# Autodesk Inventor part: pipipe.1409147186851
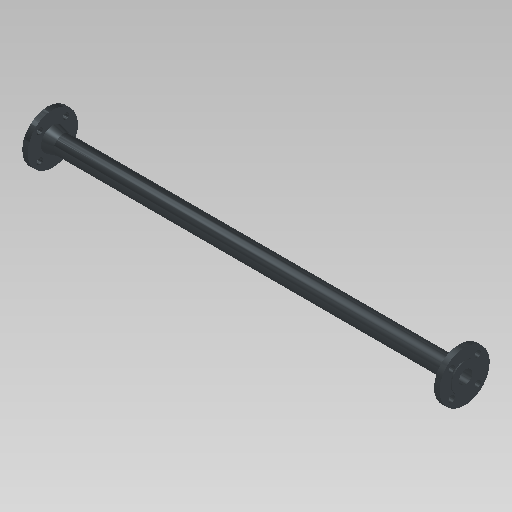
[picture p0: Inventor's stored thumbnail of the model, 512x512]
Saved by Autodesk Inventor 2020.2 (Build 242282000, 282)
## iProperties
Manager: www.cadconsulting.pl
Company: Fabian Stasiak CAD Consulting
IsCustomPart: 1
NAME: PIPING: ISO 2531 Pipe with Integrally Cast Flanges
DATA: <meta><inlinegroups number="1" deflen="50"></inlinegroups><connections number="2"></connections><angles><a>3.14159265358979</a></angles></meta>
Created: 2014-08
Material: Żeliwo sferoidalne
Description: Rury, łączniki, akcesoria z żeliwa sferoidalnego i ich złącza do zastosowań w instalacjach wodnych lub gazowych - Rura odlewana wraz z kołnierzami
Document SubType Name: Modeling
Standard: ISO 2531
Designer: F.Stasiak
Standard Revision: Fifth edition 1998-08-15
Standards Organization: ISO
Language: pl-PL
Size Designation: DN40 PN 10 - 500
Categories: <MemberInstance><Categories><Category DisplayName="Rury cienko- i grubościenne" InternalName="4347fa0f-2144-441d-94cd-e3e15c92b736" Mnemonic="TUBEANDPIPE"><Cate
Stock Number: ISO 2531 Rura odlewana wraz z kołnierzami DN40 PN 10
Density: 7.15 g/cm^3
Appearance: Ciemnoszary
Catalog Web Link: www.expertbooks.pl
L: 1250,000 mm
PL: 1250,000 mm
Author: F.Stasiak
Subject: Zbiór ćwiczeń. Autodesk Inventor 2020. Kurs Professional
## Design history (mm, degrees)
sketch "Sketch1"
  geometry: L1 (0, 0)-(-625, 0); L2 (-625, 0)-(-625, 20); L3 (-1201.144, 27)-(-48.856, 27); L4 (-48.856, 27)-(-19, 35); L5 (-19, 35)-(-19, 75); L6 (-19, 75)-(-3, 75); L7 (-3, 75)-(-3, 42); L8 (-3, 42)-(0, 42); L9 (0, 42)-(0, 20); L10 (-1250, 20)-(0, 20); L11 (0, 20)-(0, 0); L12 (-1201.144, 27)-(-1231, 35); L13 (-1231, 35)-(-1231, 75); L14 (-1231, 75)-(-1247, 75); L15 (-1247, 75)-(-1247, 42); L16 (-1247, 42)-(-1250, 42); L17 (-1250, 42)-(-1250, 20); L18 (-1250, 20)-(-1250, 0); 2 further points
  constraints: 36 end point, 9 symmetric about line, 4 parallel, 2 coincident, 2 horizontal, 2 perpendicular, 1 collinear, 1 midpoint, 1 vertical, 7 other
  dimensions: "d0" = 7 distance between parallel lines of L10 L3 (= e); "d2" = 84 diameter of L8 L1 (= d1); "d3" = 3 distance of L7.end L8.end (= f1); "d4" = 19 distance between parallel lines of L9 L5 (= C7); "d5" = 150 diameter of L6 L1 (= D); "d6" = 70 diameter of L4.end L1 (= N3); "d7" = 15 deg angle of L3 L4; "d14" = 1250 distance between parallel lines of L9 L17 (= L); "d15" = 40 diameter of L10 L1 (= ID)
revolve "Revolution1" sketch "Sketch1" stored, may be unused: angle "d10" = 90 deg
sketch "Sketch2"
  geometry: L1 (-55, 0)-(0, 0); L2 (0, 0)-(-38.891, 38.891); C1 r 75 at (0, 0) reference; C2 r 42 at (0, 0) reference; C3 r 9.5 at (-38.891, 38.891); A1 r 55 centre (0, 0) between (-55, 0) and (-38.891, 38.891)
  constraints: 4 end point, 2 centre point, 2 point on circle, 1 coincident, 1 concentric, 1 horizontal
  dimensions: "d8" = 110 diameter of A1 (= K1); "d17" = 19 diameter of C3 (= L2); "d18" = 45 deg angle of L1 L2 (computed from NU)
extrude "Extrusion1" cut sketch "Sketch2" extent not by distance; taper "d9" = 0 deg; stored distance "d13" = 10
pattern_circular "Circular Pattern1" dims angle "d12" = 360 deg
workaxis "Work Axis1"
workpoint "Work Point1"
workaxis "Work Axis2"
workpoint "Work Point2"
body "Solid1"
other parameters: "e" = 7 [user parameter; used in 2 equation terms], "N3" = 70 [user parameter; used in 2 equation terms], "C7" = 19 [user parameter; used in 2 equation terms], "f1" = 3 [user parameter; used in 1 equation term], "d1" = 84 [user parameter; used in 1 equation term], "D" = 150 [user parameter; used in 1 equation term], "K1" = 110 [user parameter; used in 1 equation term], "L2" = 19 [user parameter; used in 1 equation term], "L" = 1250 (= PL) [user parameter; used in 1 equation term], "ID" = 40 [user parameter; used in 2 equation terms], "OD" = 54 [user parameter], "PL" = 1250 [user parameter; used in 1 equation term], "Size_Designation" = 12.345 [user parameter], "PLmin" = 107.21281 (= -7.4641 x e - 3.73205 x ID + 3.73205 x N3 + 2.5 x C7) [user parameter]
